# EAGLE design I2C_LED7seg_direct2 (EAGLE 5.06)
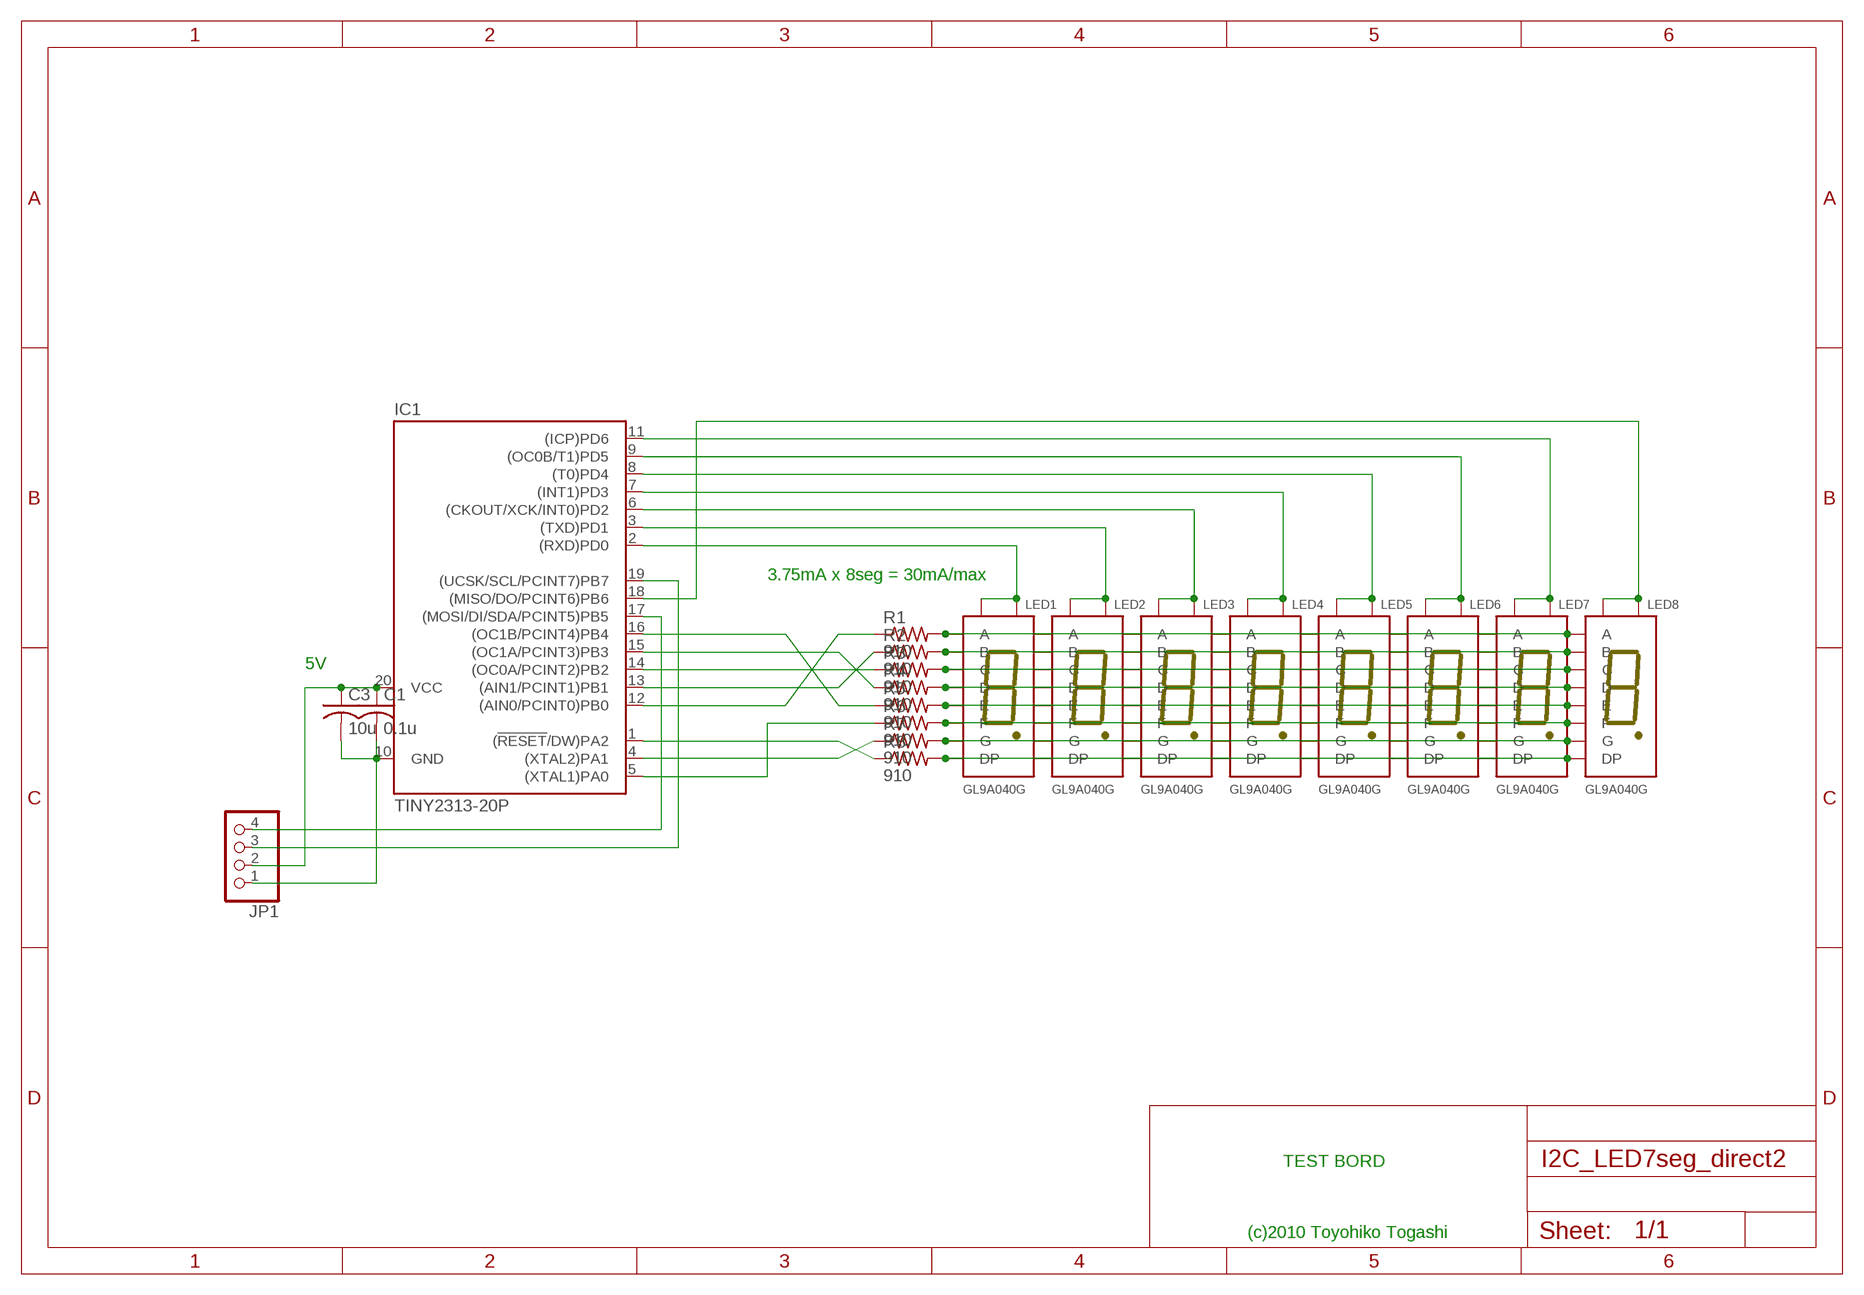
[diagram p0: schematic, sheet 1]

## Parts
C1  0.1u  C-US025-025X050  [C025-025X050]
C3  10u  C-US025-025X050  [C025-025X050]
IC1  TINY2313-20P  [DIL20]
JP1  PINHD-1X4  [1X04]
LED1  GL9A040G  [GL9A040G]
LED2  GL9A040G  [GL9A040G]
LED3  GL9A040G  [GL9A040G]
LED4  GL9A040G  [GL9A040G]
LED5  GL9A040G  [GL9A040G]
LED6  GL9A040G  [GL9A040G]
LED7  GL9A040G  [GL9A040G]
LED8  GL9A040G  [GL9A040G]
R1  910  R-US_0204/5  [0204/5]
R2  910  R-US_0204/5  [0204/5]
R3  910  R-US_0204/5  [0204/5]
R4  910  R-US_0204/5  [0204/5]
R5  910  R-US_0204/5  [0204/5]
R6  910  R-US_0204/5  [0204/5]
R7  910  R-US_0204/5  [0204/5]
R8  910  R-US_0204/5  [0204/5]

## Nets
N$1: C1.1 C3.1 IC1.20(VCC) JP1.2
N$2: LED1.P$10(A) LED2.P$10(A) LED3.P$10(A) LED4.P$10(A) LED5.P$10(A) LED6.P$10(A) LED7.P$10(A) LED8.P$10(A) R1.2
N$3: IC1.19((UCSK/SCL/PCINT7)PB7) JP1.3
N$4: IC1.17((MOSI/DI/SDA/PCINT5)PB5) JP1.4
N$6: LED1.P$9(B) LED2.P$9(B) LED3.P$9(B) LED4.P$9(B) LED5.P$9(B) LED6.P$9(B) LED7.P$9(B) LED8.P$9(B) R2.2
N$7: LED1.P$8(C) LED2.P$8(C) LED3.P$8(C) LED4.P$8(C) LED5.P$8(C) LED6.P$8(C) LED7.P$8(C) LED8.P$8(C) R3.2
N$8: LED1.P$5(D) LED2.P$5(D) LED3.P$5(D) LED4.P$5(D) LED5.P$5(D) LED6.P$5(D) LED7.P$5(D) LED8.P$5(D) R4.2
N$9: LED1.P$4(E) LED2.P$4(E) LED3.P$4(E) LED4.P$4(E) LED5.P$4(E) LED6.P$4(E) LED7.P$4(E) LED8.P$4(E) R5.2
N$10: LED1.P$2(F) LED2.P$2(F) LED3.P$2(F) LED4.P$2(F) LED5.P$2(F) LED6.P$2(F) LED7.P$2(F) LED8.P$2(F) R6.2
N$11: LED1.P$7(DP) LED2.P$7(DP) LED3.P$7(DP) LED4.P$7(DP) LED5.P$7(DP) LED6.P$7(DP) LED7.P$7(DP) LED8.P$7(DP) R8.2
N$12: LED1.P$3(G) LED2.P$3(G) LED3.P$3(G) LED4.P$3(G) LED5.P$3(G) LED6.P$3(G) LED7.P$3(G) LED8.P$3(G) R7.2
N$14: IC1.5((XTAL1)PA0) R6.1
N$15: IC1.4((XTAL2)PA1) R7.1
N$16: IC1.1((!RESET!/DW)PA2) R8.1
N$17: IC1.12((AIN0/PCINT0)PB0) R1.1
N$19: IC1.13((AIN1/PCINT1)PB1) R2.1
N$20: IC1.14((OC0A/PCINT2)PB2) R3.1
N$21: IC1.15((OC1A/PCINT3)PB3) R4.1
N$22: IC1.16((OC1B/PCINT4)PB4) R5.1
N$25: IC1.2((RXD)PD0) LED1.P$1(CA1) LED1.P$6(CA6)
N$28: IC1.18((MISO/DO/PCINT6)PB6) LED8.P$1(CA1) LED8.P$6(CA6)
N$33: C1.2 C3.2 IC1.10(GND) JP1.1
N$98: IC1.3((TXD)PD1) LED2.P$1(CA1) LED2.P$6(CA6)
N$99: IC1.6((CKOUT/XCK/INT0)PD2) LED3.P$1(CA1) LED3.P$6(CA6)
N$100: IC1.7((INT1)PD3) LED4.P$1(CA1) LED4.P$6(CA6)
N$101: IC1.8((T0)PD4) LED5.P$1(CA1) LED5.P$6(CA6)
N$102: IC1.9((OC0B/T1)PD5) LED6.P$1(CA1) LED6.P$6(CA6)
N$103: IC1.11((ICP)PD6) LED7.P$1(CA1) LED7.P$6(CA6)

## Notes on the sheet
- 3.75mA x 8seg = 30mA/max
- 5V
- TEST BORD
- (c)2010 Toyohiko Togashi

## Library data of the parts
C1 C3 = rcl:C-US: CAPACITOR, American symbol
IC1 = TOG:TINY2313: 8-bit AVR Microcontroller with 2K Bytes Flash Source: http://www.atmel.com .. doc2543.pdf
JP1 = pinhead:PINHD-1X4: PIN HEADER
LED1-LED8 = TOG:GL9A040G: 7 Segment LED
R1-R8 = rcl:R-US_: RESISTOR, American symbol

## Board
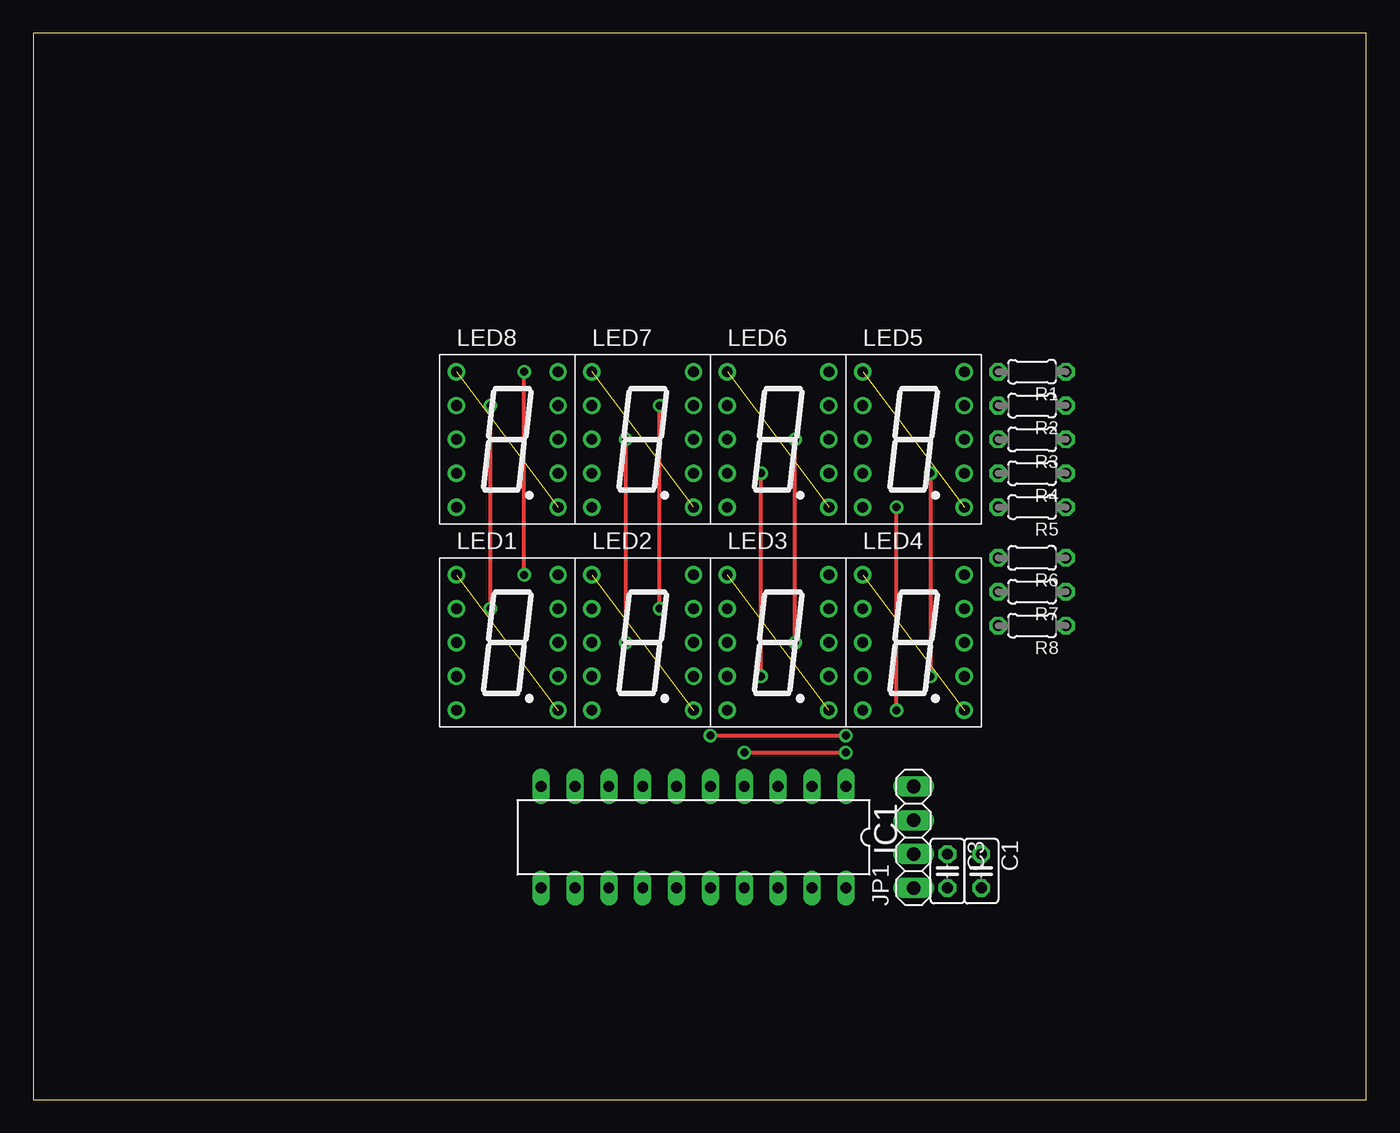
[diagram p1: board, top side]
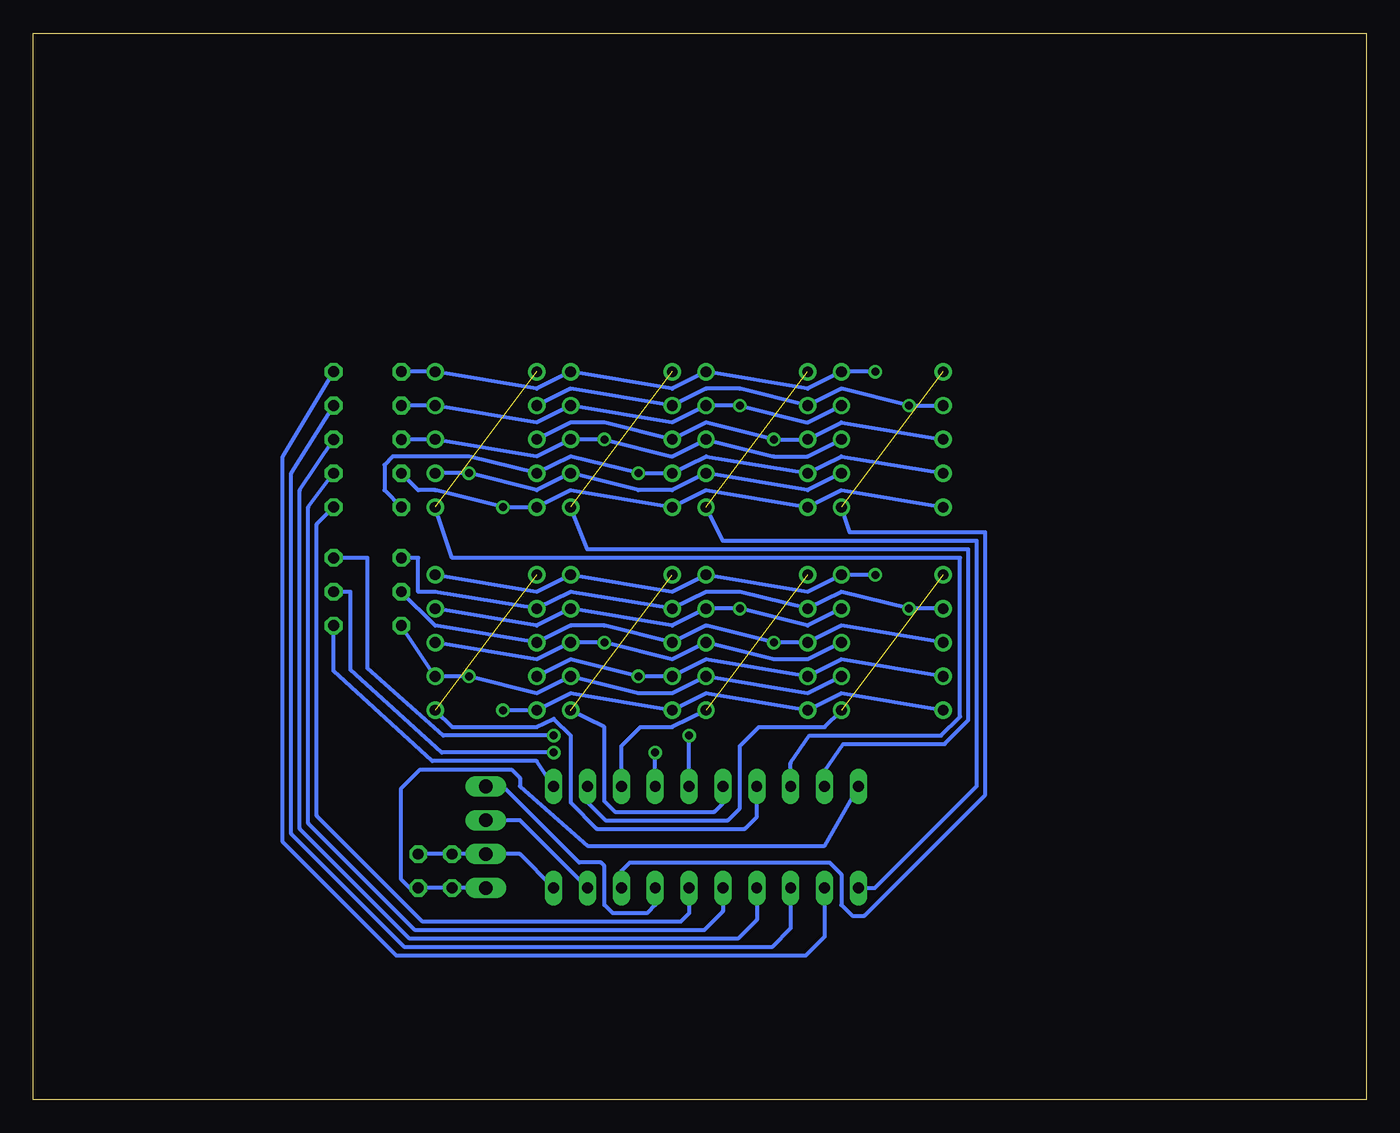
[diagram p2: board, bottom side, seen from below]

Size 100 x 80 mm. Coordinates in mm from the lower left corner, seen from the top.
Outline: 0,0 100,0 100,80 0,80 0,0
Copper layers (1*16): Top 0.035mm / dielectric 1.5mm / Bottom 0.035mm
Design rules "default": minimum track width 10mil, minimum drill 24mil, track to track 8mil, track to pad 8mil, pad to pad 8mil, via to via 8mil, smd to smd 8mil, copper to edge 40mil, drill to drill 8mil, minimum pad ring 10mil, minimum via ring 8mil, stop-mask expansion 4mil, vias tented up to drill 0mil, thermal gap 10mil

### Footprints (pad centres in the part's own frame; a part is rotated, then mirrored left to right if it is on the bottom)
C025-025X050 = drill 0.813 octagon: 1 -1.27,0; 2 1.27,0
DIL20 = drill 0.813 long: 1 -11.43,-3.81; 2 -8.89,-3.81; 3 -6.35,-3.81; 4 -3.81,-3.81; 5 -1.27,-3.81; 6 1.27,-3.81; 7 3.81,-3.81; 8 6.35,-3.81; 9 8.89,-3.81; 10 11.43,-3.81; 11 11.43,3.81; 12 8.89,3.81; 13 6.35,3.81; 14 3.81,3.81; 15 1.27,3.81; 16 -1.27,3.81; 17 -3.81,3.81; 18 -6.35,3.81; 19 -8.89,3.81; 20 -11.43,3.81
1X04 = drill 1.016 long: 1 -3.81,0; 2 -1.27,0; 3 1.27,0; 4 3.81,0
GL9A040G = drill 0.8 round: P$1 -3.81,5.08; P$2 -3.81,2.54; P$3 -3.81,0; P$4 -3.81,-2.54; P$5 -3.81,-5.08; P$6 3.81,-5.08; P$7 3.81,-2.54; P$8 3.81,0; P$9 3.81,2.54; P$10 3.81,5.08
0204/5 = drill 0.813 octagon: 1 -2.54,0; 2 2.54,0

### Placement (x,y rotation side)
C1  71.12,17.14 270 top
C3  68.58,17.14 270 top
IC1  49.53,19.68 180 top
JP1  66.04,19.68 90 top
LED1  35.56,34.29 0 top
LED2  45.72,34.29 0 top
LED3  55.88,34.29 0 top
LED4  66.04,34.29 0 top
LED5  66.04,49.53 0 top
LED6  55.88,49.53 0 top
LED7  45.72,49.53 0 top
LED8  35.56,49.53 0 top
R1  74.93,54.61 180 top
R2  74.93,52.07 180 top
R3  74.93,49.53 180 top
R4  74.93,46.99 180 top
R5  74.93,44.45 180 top
R6  74.93,40.64 180 top
R7  74.93,38.1 180 top
R8  74.93,35.56 180 top

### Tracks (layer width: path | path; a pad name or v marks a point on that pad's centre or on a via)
N$1
  Bottom 0.305: IC1.20 63.5,18.41 JP1.2 C3.1 C1.1
N$2  (via drill 0.6)
  Top 0.305: v36.83,39.37 v36.83,54.61
  Bottom 0.305: v36.83,54.61 LED8.P$10 41.91,53.34 LED7.P$10 52.07,53.34 LED6.P$10 62.23,53.34 LED5.P$10 R1.2 | v36.83,39.37 LED1.P$10 41.91,38.1 LED2.P$10 52.07,38.1 LED3.P$10 62.23,38.1 LED4.P$10
N$3
  Bottom 0.305: IC1.19 63.5,20.95 JP1.3
N$4
  Bottom 0.305: IC1.17 53.34,14.61 53.98,13.97 56.52,13.97 57.15,14.61 57.15,17.52 57.41,17.78 59.05,17.78 64.77,23.5
  Bottom 0.406: 64.77,23.5 JP1.4
N$6  (via drill 0.6)
  Top 0.305: v46.99,36.83 v46.99,52.07
  Bottom 0.305: LED8.P$9 41.91,50.8 v46.99,52.07 LED7.P$9 52.07,50.8 LED6.P$9 62.23,50.8 LED5.P$9 R2.2 | LED1.P$9 41.91,35.56 v46.99,36.83 LED2.P$9 52.07,35.56 LED3.P$9 62.23,35.56 LED4.P$9
N$7  (via drill 0.6)
  Top 0.305: v57.15,34.29 v57.15,49.53
  Bottom 0.305: LED8.P$8 41.91,48.26 44.45,48.26 LED7.P$8 52.07,48.26 v57.15,49.53 LED6.P$8 62.23,48.26 LED5.P$8 R3.2 | LED1.P$8 41.91,33.02 44.45,33.02 LED2.P$8 52.07,33.02 v57.15,34.29 LED3.P$8 62.23,33.02 LED4.P$8
N$8  (via drill 0.6)
  Top 0.305: v64.77,29.21 v64.77,44.45
  Bottom 0.305: v64.77,29.21 LED4.P$5 59.69,30.48 LED3.P$5 49.53,30.48 LED2.P$5 39.37,30.48 LED1.P$5 | LED8.P$5 39.37,45.72 LED7.P$5 49.53,45.72 LED6.P$5 59.69,45.72 LED5.P$5 v64.77,44.45 69.85,45.72 71.12,45.72 R4.2
N$9  (via drill 0.6)
  Top 0.305: v54.61,31.75 v54.61,46.99
  Bottom 0.305: LED8.P$4 39.37,48.26 LED7.P$4 49.53,48.26 LED6.P$4 v54.61,46.99 59.69,48.26 LED5.P$4 67.31,48.26 73.03,48.26 73.66,47.62 73.66,45.72 R5.2 | LED1.P$4 39.37,33.02 LED2.P$4 49.53,33.02 LED3.P$4 v54.61,31.75 59.69,33.02 LED4.P$4
N$10  (via drill 0.6)
  Top 0.305: v34.29,36.83 v34.29,52.07
  Bottom 0.305: LED8.P$2 v34.29,52.07 39.37,53.34 LED7.P$2 46.99,53.34 49.53,53.34 LED6.P$2 59.69,53.34 LED5.P$2 | LED1.P$2 v34.29,36.83 39.37,38.1 LED2.P$2 46.99,38.1 49.53,38.1 LED3.P$2 59.69,38.1 LED4.P$2 69.85,38.1 71.12,38.1 71.12,40.64 R6.2
N$11  (via drill 0.6)
  Top 0.305: v67.31,46.99 v67.31,31.75
  Bottom 0.305: LED5.P$7 v67.31,46.99 62.23,45.72 LED6.P$7 54.61,45.72 52.07,45.72 LED7.P$7 41.91,45.72 LED8.P$7 | LED1.P$7 41.91,30.48 LED2.P$7 52.07,30.48 54.61,30.48 LED3.P$7 62.23,30.48 v67.31,31.75 LED4.P$7 R8.2
N$12  (via drill 0.6)
  Top 0.305: v44.45,34.29 v44.45,49.53
  Bottom 0.305: LED8.P$3 39.37,50.8 LED7.P$3 v44.45,49.53 49.53,50.8 LED6.P$3 57.15,50.8 59.69,50.8 LED5.P$3 | LED1.P$3 39.37,35.56 LED2.P$3 v44.45,34.29 49.53,35.56 LED3.P$3 57.15,35.56 59.69,35.56 LED4.P$3 69.85,35.56 R7.2
N$14  (via drill 0.6)
  Top 0.305: v50.8,27.3 v60.96,27.3
  Bottom 0.305: IC1.5 v50.8,27.3 | v60.96,27.3 69.25,27.3 74.93,32.35 74.93,40.64 R6.1
N$15  (via drill 0.6)
  Top 0.305: v53.34,26.04 v60.96,26.04
  Bottom 0.305: IC1.4 v53.34,26.04 | v60.96,26.04 69.36,26.04 76.2,32.24 76.2,38.1 R7.1
N$16
  Bottom 0.305: IC1.1 62.23,25.4 70.06,25.4 77.47,32.17 R8.1
N$17
  Bottom 0.305: IC1.12 40.64,12.21 42.06,10.79 72.76,10.79 81.28,19.31 81.28,48.26 R1.1
N$19
  Bottom 0.305: IC1.13 43.18,12.85 44.6,11.43 72.13,11.43 80.64,19.95 80.64,46.99 R2.1
N$20
  Bottom 0.305: IC1.14 45.72,13.48 47.14,12.06 71.75,12.06 80.01,20.32 80.01,45.72 R3.1
N$21
  Bottom 0.305: IC1.15 48.26,14.12 49.68,12.7 71.34,12.7 79.38,20.73 79.38,44.45 R4.1
N$22
  Bottom 0.305: IC1.16 50.8,13.97 51.44,13.34 70.78,13.34 78.74,21.29 78.74,43.18 R5.1
N$25  (1 unrouted)
  Bottom 0.305: IC1.2 58.42,22.3 57.07,20.95 47.89,20.95 46.99,21.85 46.99,26.52 45.57,27.94 40.64,27.94 LED1.P$6
N$28  (1 unrouted)
  Bottom 0.305: IC1.18 55.88,17.14 55.24,17.78 40.27,17.78 39.37,16.88 39.37,14.61 38.55,13.78 37.65,13.78 28.57,22.86 28.57,42.55 38.73,42.55 LED8.P$6
N$33
  Bottom 0.305: JP1.1 C3.2 C1.2 71.75,15.88 72.39,16.51 72.39,23.34 70.97,24.77 64.14,24.77 63.5,24.13 63.5,23.5 58.42,19.05 40.64,19.05 IC1.10
N$98  (1 unrouted)
  Bottom 0.305: LED2.P$6 52.07,27.94 54.46,27.94 55.88,26.52 IC1.3
N$99  (1 unrouted)
  Bottom 0.305: LED3.P$6 57.15,27.94 57.15,22.38 56.37,21.59 48.9,21.59 48.26,22.23 IC1.6
N$100  (1 unrouted)
  Bottom 0.305: LED4.P$6 68.58,27.94 62.23,27.94 60.96,28.57 59.69,27.3 59.69,22.28 57.73,20.32 46.62,20.32 45.72,21.22 IC1.7
N$101  (1 unrouted)
  Bottom 0.305: IC1.8 43.18,25.25 41.76,27.3 31.9,27.3 30.48,28.73 30.48,40.64 68.58,40.64 LED5.P$6
N$102  (1 unrouted)
  Bottom 0.305: IC1.9 40.64,24.61 39.22,26.67 31.64,26.67 29.84,28.47 29.84,41.27 58.42,41.27 LED6.P$6
N$103  (1 unrouted)
  Bottom 0.305: IC1.11 36.86,15.88 29.21,23.52 29.21,41.91 48.26,41.91 LED7.P$6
